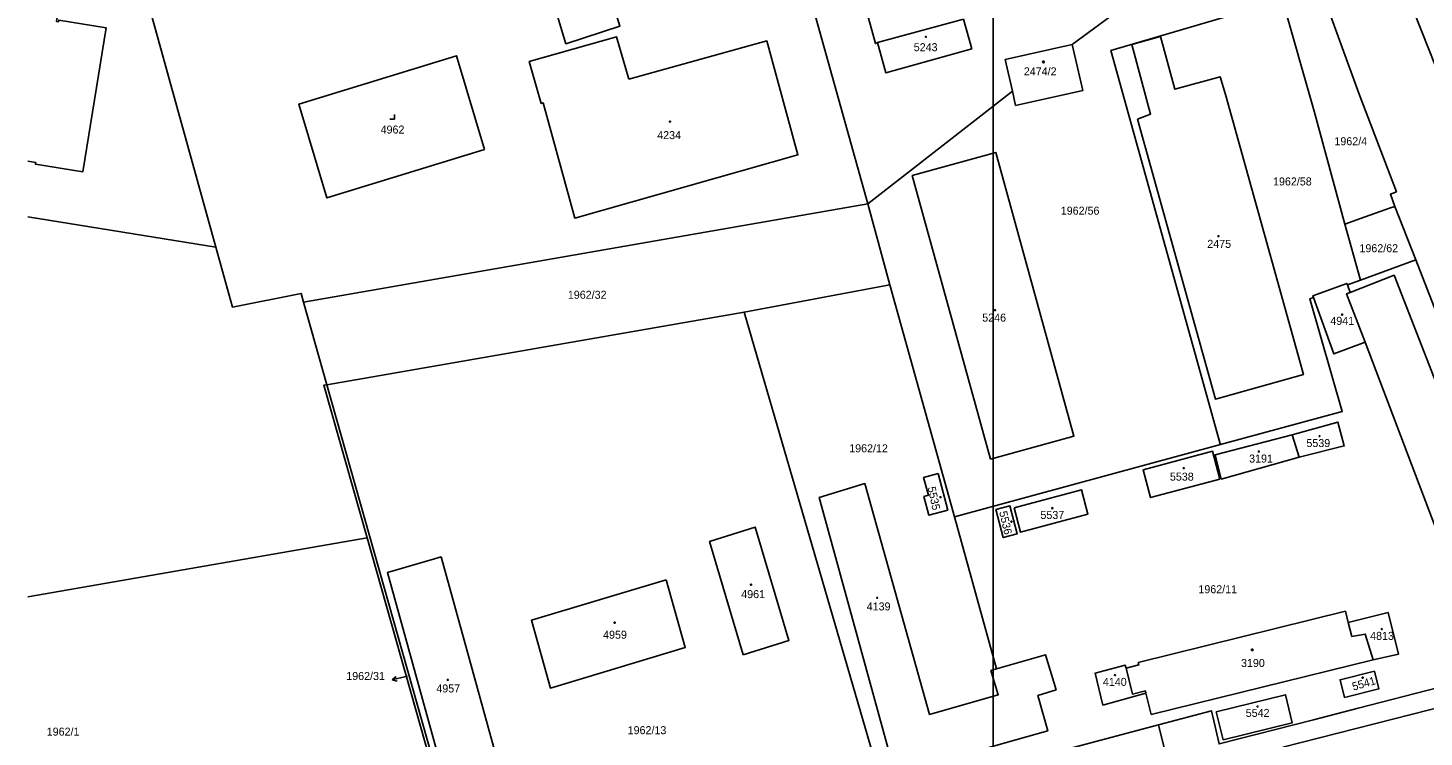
# Model space of a CAD drawing. Extents: x -667048 to -665920, y -1108425 to -1107247.
# Drawn here: x -667043.5 to -666746.8, y -1108016.8 to -1107866.2 of the extents above; entities that cross this region are included whole.
import ezdxf

# ---------------------------------------------------------------- set-up
doc = ezdxf.new("R2010")
doc.units = 0
for name, color, linetype in [('Default', 7, 'Continuous'), ('Hranice parcel', 7, 'Continuous'), ('Parcelní čísla', 7, 'Continuous'), ('Pop_ PČ_ popisy', 7, 'Continuous'), ('Vrstva 2', 7, 'Continuous'), ('Značky budov', 7, 'Continuous'), ('Značky kultur', 7, 'Continuous')]:
    doc.layers.add(name, color=color, linetype=linetype)

# ---------------------------------------------------------------- blocks, each defined once
blk = doc.blocks.new('3.191')
at = {"layer": 'Default'}
for p, q in [((-1000, 0), (0, 0)), ((0, 0), (0, 1000))]:
    blk.add_line(p, q, dxfattribs=at)
blk = doc.blocks.new('4.021')
at = {"layer": 'Default'}
blk.add_circle((-7, 1), 175, dxfattribs=at)
blk = doc.blocks.new('10291')
at = {"layer": 'Default'}
for p, q in [((0, 3001), (-500, 2001)), ((0, 1), (0, 3001)), ((0, 3001), (500, 2001))]:
    blk.add_line(p, q, dxfattribs=at)

msp = doc.modelspace()

# ---------------------------------------------------------------- linework, layer by layer
at = {"layer": 'Hranice parcel'}
for points in [[(-666752.66, -1107901.06), (-666760.59, -1107880.31), (-666775.34, -1107839.8), (-666801.53, -1107771.67)], [(-666862.97, -1107869.35), (-666863.4, -1107869.55), (-666879.8, -1107810.04)], [(-667030.05, -1107817.21), (-667003.54, -1107912.79)], [(-666942.5, -1107825.4), (-666931.02, -1107821.66), (-666917.67, -1107865.87), (-666929.14, -1107869.61), (-666942.5, -1107825.4)], [(-666742.75, -1107878.49), (-666761.63, -1107830.87)], [(-667043.46, -1107846.47), (-667034.62, -1107847.92), (-667037.37, -1107864.87), (-667036.96, -1107864.94), (-667036.89, -1107864.56), (-667026.84, -1107866.2), (-667031.79, -1107896.83), (-667041.86, -1107895.2), (-667041.79, -1107894.82), (-667043.46, -1107894.55)], [(-666864.97, -1107903.57), (-666878.29, -1107855.87)], [(-666821.56, -1107869.77), (-666811.21, -1107862.12)], [(-666790.1, -1107954.73), (-666790.14, -1107954.57), (-666813.39, -1107871), (-666776.91, -1107860.29)], [(-666776.91, -1107860.29), (-666770.16, -1107883.94)], [(-666844.66, -1107864.39), (-666842.92, -1107870.69), (-666861.2, -1107875.75), (-666862.97, -1107869.35)], [(-666862.97, -1107869.35), (-666844.66, -1107864.39)], [(-666915.81, -1107877.13), (-666886.49, -1107868.98), (-666879.86, -1107893.17), (-666927.26, -1107906.63), (-666933.98, -1107882.15), (-666934.38, -1107882.26), (-666936.95, -1107873.38), (-666918.43, -1107868.1), (-666915.81, -1107877.13)], [(-666808.92, -1107869.75), (-666802.85, -1107868.08), (-666799.76, -1107879.27), (-666790.12, -1107876.61), (-666789.04, -1107880.39), (-666772.47, -1107939.84), (-666791.16, -1107945.04), (-666807.74, -1107885.6)], [(-666835.8, -1107872.96), (-666821.56, -1107869.77)], [(-666821.56, -1107869.77), (-666819.34, -1107879.56), (-666833.61, -1107882.73)], [(-666807.74, -1107885.6), (-666804.94, -1107884.54), (-666808.92, -1107869.75)], [(-666946.48, -1107892.05), (-666979.94, -1107902.32), (-666985.89, -1107882.41), (-666952.43, -1107872.14), (-666946.48, -1107892.05)], [(-666834.29, -1107879.68), (-666835.8, -1107872.96)], [(-666864.97, -1107903.57), (-666834.29, -1107879.68)], [(-666833.61, -1107882.73), (-666834.29, -1107879.68)], [(-666770.16, -1107883.94), (-666763.69, -1107907.88)], [(-666838.96, -1107957.81), (-666855.57, -1107897.58), (-666837.81, -1107892.67), (-666821.2, -1107952.91), (-666838.96, -1107957.81)], [(-666984.9, -1107924.44), (-666864.97, -1107903.57)], [(-666860.34, -1107920.82), (-666864.97, -1107903.57)], [(-666753, -1107904.13), (-666753.96, -1107901.57), (-666752.66, -1107901.06)], [(-667003.54, -1107912.79), (-667043.46, -1107906.32)], [(-666763.69, -1107907.88), (-666760.35, -1107906.71), (-666754.14, -1107904.53), (-666753, -1107904.13)], [(-666748.56, -1107915.51), (-666753, -1107904.13)], [(-666760.36, -1107919.81), (-666763.69, -1107907.88)], [(-667003.54, -1107912.79), (-667000.02, -1107925.53), (-666985.4, -1107922.66), (-666984.9, -1107924.44)], [(-666748.56, -1107915.51), (-666760.36, -1107919.81)], [(-666738.77, -1107940.63), (-666748.56, -1107915.51)], [(-666860.34, -1107920.82), (-666891.29, -1107926.58)], [(-666846.6, -1107970.04), (-666860.34, -1107920.82)], [(-666770.31, -1107923.47), (-666770.44, -1107923.12), (-666763.24, -1107920.49), (-666763.11, -1107920.82)], [(-666760.36, -1107919.81), (-666763.11, -1107920.82)], [(-666763.11, -1107920.82), (-666762.51, -1107922.39)], [(-666762.51, -1107922.39), (-666753.19, -1107918.76), (-666739.9, -1107952.71), (-666736.11, -1107951.3)], [(-666979.93, -1107942.01), (-666984.9, -1107924.44)], [(-666770.31, -1107923.47), (-666771.09, -1107923.76), (-666764.2, -1107947.71), (-666790.1, -1107954.73)], [(-666759.34, -1107933), (-666766.01, -1107935.47), (-666770.31, -1107923.47)], [(-666762.51, -1107922.39), (-666763.27, -1107922.67), (-666759.34, -1107933)], [(-666891.29, -1107926.58), (-666979.93, -1107942.01)], [(-666891.29, -1107926.58), (-666861.25, -1108029.69)], [(-666735.81, -1107994.89), (-666759.34, -1107933)], [(-666971.4, -1107974.51), (-666980.6, -1107942.13), (-666979.93, -1107942.01)], [(-666979.93, -1107942.01), (-666948.55, -1108052.87)], [(-666774.85, -1107952.63), (-666765.14, -1107949.95), (-666763.79, -1107955.01), (-666773.35, -1107957.42)], [(-666773.35, -1107957.42), (-666789.9, -1107962.03), (-666791.24, -1107956.92), (-666774.85, -1107952.63)], [(-666773.35, -1107957.42), (-666774.85, -1107952.63)], [(-666790.1, -1107954.73), (-666846.6, -1107970.04)], [(-666790.23, -1107962.05), (-666804.95, -1107965.97), (-666806.52, -1107960.05), (-666791.8, -1107956.13), (-666790.23, -1107962.05)], [(-666833.56, -1108017.4), (-666859.17, -1108024.68), (-666875.35, -1107965.92), (-666865.66, -1107962.99), (-666851.87, -1108012.02), (-666837.29, -1108007.83), (-666838.85, -1108002.7), (-666837.63, -1108002.35)], [(-666850.09, -1107960.86), (-666848.02, -1107968.61), (-666852.05, -1107969.68), (-666853.1, -1107965.71), (-666852.14, -1107965.45), (-666853.14, -1107961.67), (-666850.09, -1107960.86)], [(-666833.93, -1107968.13), (-666819.61, -1107964.32), (-666818.23, -1107969.5), (-666832.55, -1107973.32), (-666833.93, -1107968.13)], [(-666837.8, -1107968.51), (-666834.82, -1107967.71), (-666833.24, -1107973.66), (-666836.22, -1107974.45), (-666837.8, -1107968.51)], [(-666846.6, -1107970.04), (-666837.63, -1108002.35)], [(-666971.4, -1107974.51), (-667043.46, -1107987.01)], [(-666957.96, -1108021.81), (-666971.4, -1107974.51)], [(-666891.49, -1107999.36), (-666898.63, -1107975.26), (-666888.92, -1107972.24), (-666881.78, -1107996.34), (-666891.49, -1107999.36)], [(-666955.64, -1107978.55), (-666941.34, -1108030.34), (-666942.51, -1108030.68), (-666952.78, -1108033.65), (-666967.07, -1107981.86), (-666957.09, -1107978.97), (-666955.64, -1107978.55)], [(-666907.83, -1107983.4), (-666903.8, -1107997.79), (-666932.46, -1108006.41), (-666936.48, -1107992.02), (-666907.83, -1107983.4)], [(-666810.14, -1108002.17), (-666807.4, -1108001.49), (-666807.53, -1108000.96), (-666763.53, -1107990.09)], [(-666763.53, -1107990.09), (-666762.93, -1107992.49)], [(-666762.93, -1107992.49), (-666754.44, -1107990.4), (-666752.24, -1107999.21), (-666757.61, -1108000.4)], [(-666762.19, -1107995.47), (-666762.93, -1107992.49)], [(-666757.61, -1108000.4), (-666759.3, -1107994.95), (-666762.19, -1107995.47)], [(-666837.63, -1108002.35), (-666827.26, -1107999.36), (-666824.99, -1108006.76), (-666828.9, -1108007.97), (-666826.78, -1108015.47), (-666833.56, -1108017.4)], [(-666805.92, -1108007.53), (-666815.05, -1108010.04), (-666816.69, -1108003.25), (-666810.32, -1108001.56), (-666810.14, -1108002.17)], [(-666757.61, -1108000.4), (-666804.81, -1108012.01)], [(-666803.23, -1108014.21), (-666792.01, -1108011.23), (-666790.36, -1108018.29), (-666770.32, -1108013.15), (-666760.82, -1108010.71), (-666743.74, -1108006.33), (-666717.9, -1107999.7)], [(-666810.14, -1108002.17), (-666808.77, -1108007.7), (-666806.04, -1108007.03)], [(-666757.37, -1108002.86), (-666756.45, -1108006.6), (-666763.75, -1108008.39), (-666764.67, -1108004.65), (-666757.37, -1108002.86)], [(-666806.04, -1108007.03), (-666805.92, -1108007.53)], [(-666804.81, -1108012.01), (-666805.92, -1108007.53)], [(-666731.16, -1108007.34), (-666741.77, -1108010.04), (-666776.85, -1108018.98)], [(-666790.99, -1108011.46), (-666776.28, -1108007.84), (-666774.82, -1108013.77), (-666789.53, -1108017.38), (-666790.99, -1108011.46)], [(-666832.27, -1108021.94), (-666803.23, -1108014.21)], [(-666792.38, -1108057.96), (-666803.23, -1108014.21)]]:
    msp.add_lwpolyline(points, dxfattribs=at)
at = {"layer": 'Pop_ PČ_ popisy'}
msp.add_lwpolyline([(-666962.79, -1108003.86), (-666963.18, -1108003.96)], dxfattribs=at)
at = {"layer": 'Vrstva 2'}
msp.add_lwpolyline([(-666838.39, -1107343.37), (-666244.39, -1107343.37), (-666244.39, -1108183.37), (-666838.39, -1108183.37)], close=True, dxfattribs=at)

# ---------------------------------------------------------------- block references
at = {"layer": 'Pop_ PČ_ popisy', "xscale": 0.0010000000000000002, "yscale": 0.0010000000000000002, "rotation": 103.99999999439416}
msp.add_blockref('10291', (-666963.18, -1108003.96), dxfattribs=at)
at = {"layer": 'Značky budov'}
for p, xscale, yscale in [((-666852.66, -1107868.12), 0.0006700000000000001, 0.0006700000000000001), ((-666827.68, -1107873.45), 0.0010000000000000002, 0.0010000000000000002), ((-666907.02, -1107886.13), 0.0006700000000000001, 0.0006700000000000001), ((-666790.49, -1107910.45), 0.0006700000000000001, 0.0006700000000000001), ((-666837.96, -1107926.18), 0.0006700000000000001, 0.0006700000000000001), ((-666764.22, -1107927.13), 0.0006700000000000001, 0.0006700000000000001), ((-666769.02, -1107952.91), 0.0006700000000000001, 0.0006700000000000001), ((-666781.93, -1107956.19), 0.0006700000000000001, 0.0006700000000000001), ((-666797.88, -1107959.72), 0.0006700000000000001, 0.0006700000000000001), ((-666849.57, -1107965.89), 0.0006700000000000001, 0.0006700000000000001), ((-666825.79, -1107968.21), 0.0006700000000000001, 0.0006700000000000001), ((-666834.49, -1107971.09), 0.0006700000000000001, 0.0006700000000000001), ((-666889.83, -1107984.46), 0.0006700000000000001, 0.0006700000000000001), ((-666863, -1107987.27), 0.0006700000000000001, 0.0006700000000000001), ((-666918.78, -1107992.54), 0.0006700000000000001, 0.0006700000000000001), ((-666755.81, -1107993.89), 0.0006700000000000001, 0.0006700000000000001), ((-666783.33, -1107998.3), 0.0010000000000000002, 0.0010000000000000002), ((-666954.24, -1108004.68), 0.0006700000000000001, 0.0006700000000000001), ((-666812.48, -1108003.66), 0.0006700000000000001, 0.0006700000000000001), ((-666759.85, -1108004.22), 0.0006700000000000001, 0.0006700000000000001), ((-666782.19, -1108010.33), 0.0006700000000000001, 0.0006700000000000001)]:
    msp.add_blockref('4.021', p, dxfattribs=dict(at, xscale=xscale, yscale=yscale))
at = {"layer": 'Značky kultur', "xscale": 0.0010000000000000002, "yscale": 0.0010000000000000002}
msp.add_blockref('3.191', (-666965.58, -1107885.6), dxfattribs=at)

# ---------------------------------------------------------------- texts
at = {"layer": 'Parcelní čísla'}
for s, p in [('5243', (-666855.25, -1107871.18)), ('2474/2', (-666831.86, -1107876.31)), ('4962', (-666968.52, -1107888.67)), ('4234', (-666909.75, -1107889.85)), ('1962/4', (-666765.87, -1107891.15)), ('1962/58', (-666778.91, -1107899.69)), ('1962/56', (-666824.01, -1107905.89)), ('2475', (-666792.88, -1107912.94)), ('1962/62', (-666760.55, -1107913.87)), ('1962/32', (-666928.74, -1107923.75)), ('5246', (-666840.69, -1107928.6)), ('4941', (-666766.74, -1107929.29)), ('5539', (-666771.82, -1107955.24)), ('1962/12', (-666868.96, -1107956.36)), ('3191', (-666783.99, -1107958.53)), ('5538', (-666800.82, -1107962.37)), ('5537', (-666828.33, -1107970.51)), ('4961', (-666891.9, -1107987.32)), ('1962/11', (-666794.77, -1107986.28)), ('4139', (-666865.24, -1107989.93)), ('4959', (-666921.25, -1107995.94)), ('4813', (-666758.28, -1107996.18)), ('3190', (-666785.71, -1108001.94)), ('1962/31', (-666975.82, -1108004.71)), ('4140', (-666815.06, -1108005.95)), ('4957', (-666956.68, -1108007.35)), ('5542', (-666784.71, -1108012.54)), ('1962/1', (-667039.46, -1108016.52)), ('1962/13', (-666916.03, -1108016.21))]:
    msp.add_text(s, height=1.7, dxfattribs=at).set_placement(p)
for s, rotation, p in [('5535', 282, (-666852.3, -1107963.82)), ('5536', 283, (-666837.11, -1107969.04)), ('5541', 16, (-666761.83, -1108006.97))]:
    msp.add_text(s, height=1.7, rotation=rotation, dxfattribs=at).set_placement(p)

doc.saveas('drawing.dxf')
